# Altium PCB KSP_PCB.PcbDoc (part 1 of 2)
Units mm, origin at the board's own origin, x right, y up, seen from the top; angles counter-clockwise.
Board outline 121 x 121 mm, 2 copper layers (Top Layer, Bottom Layer), stack 1.571 mm thick; 210 components, 141 nets, 724 pads, 132 vias.
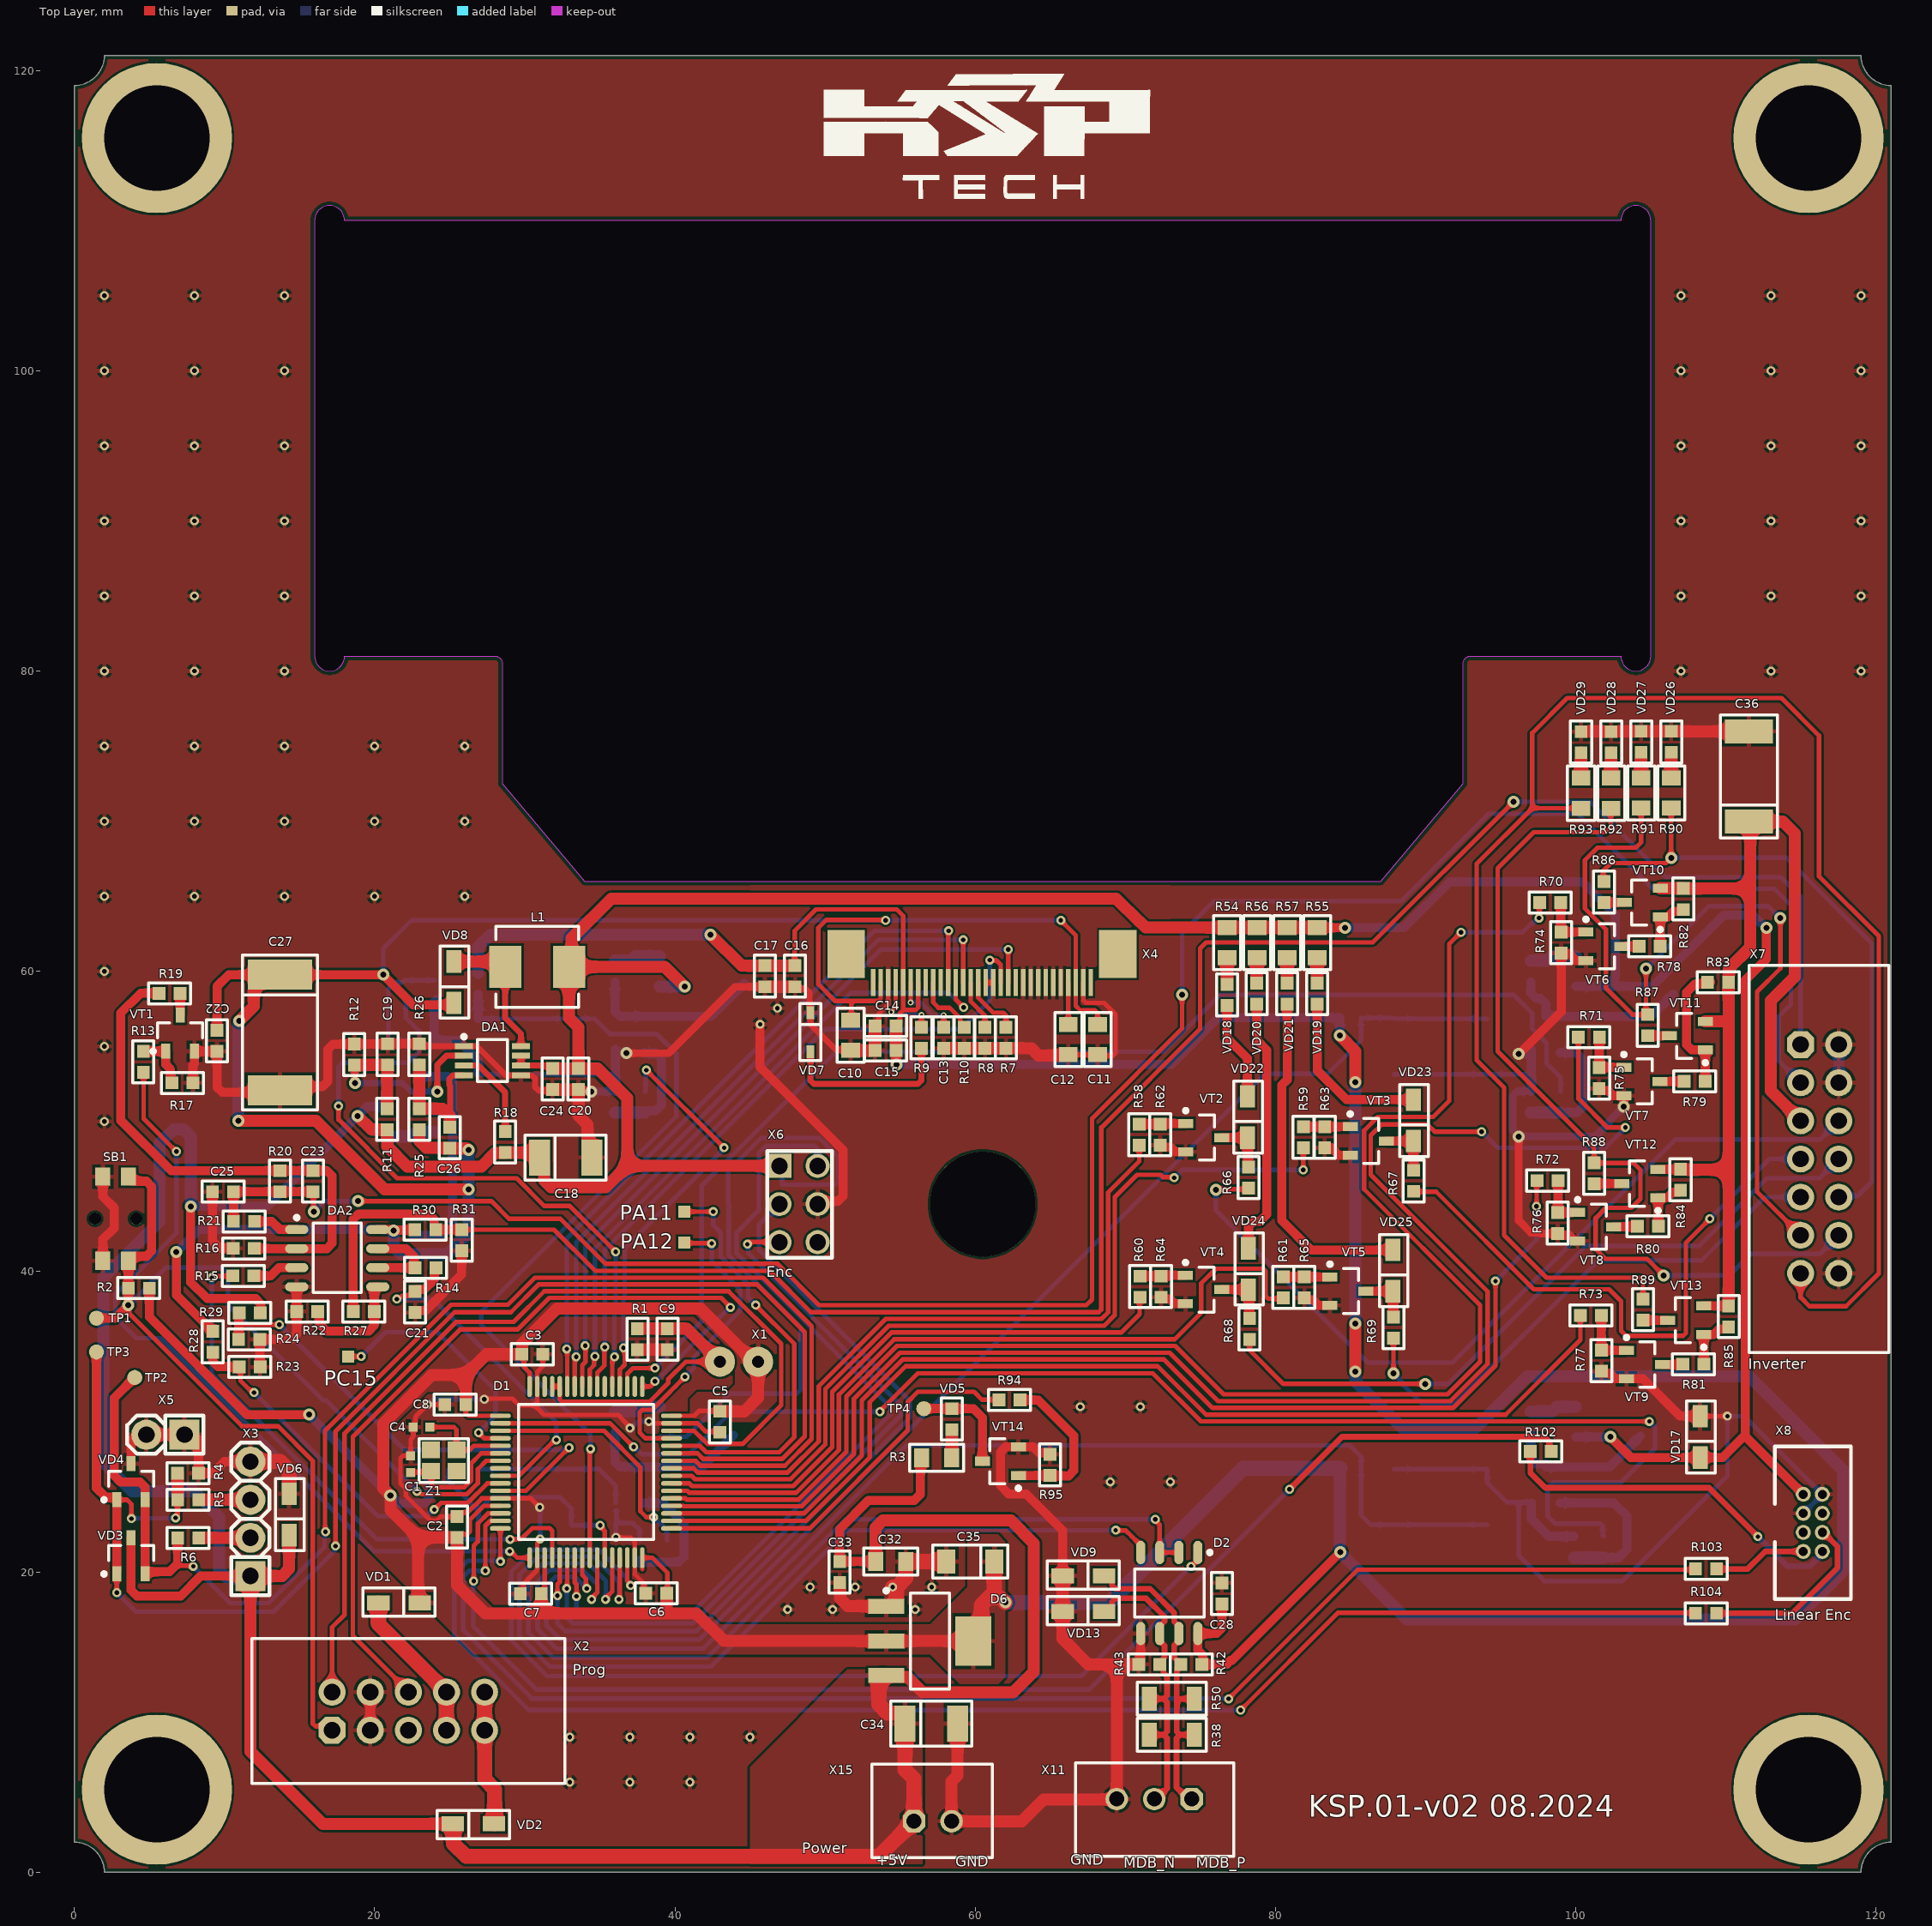
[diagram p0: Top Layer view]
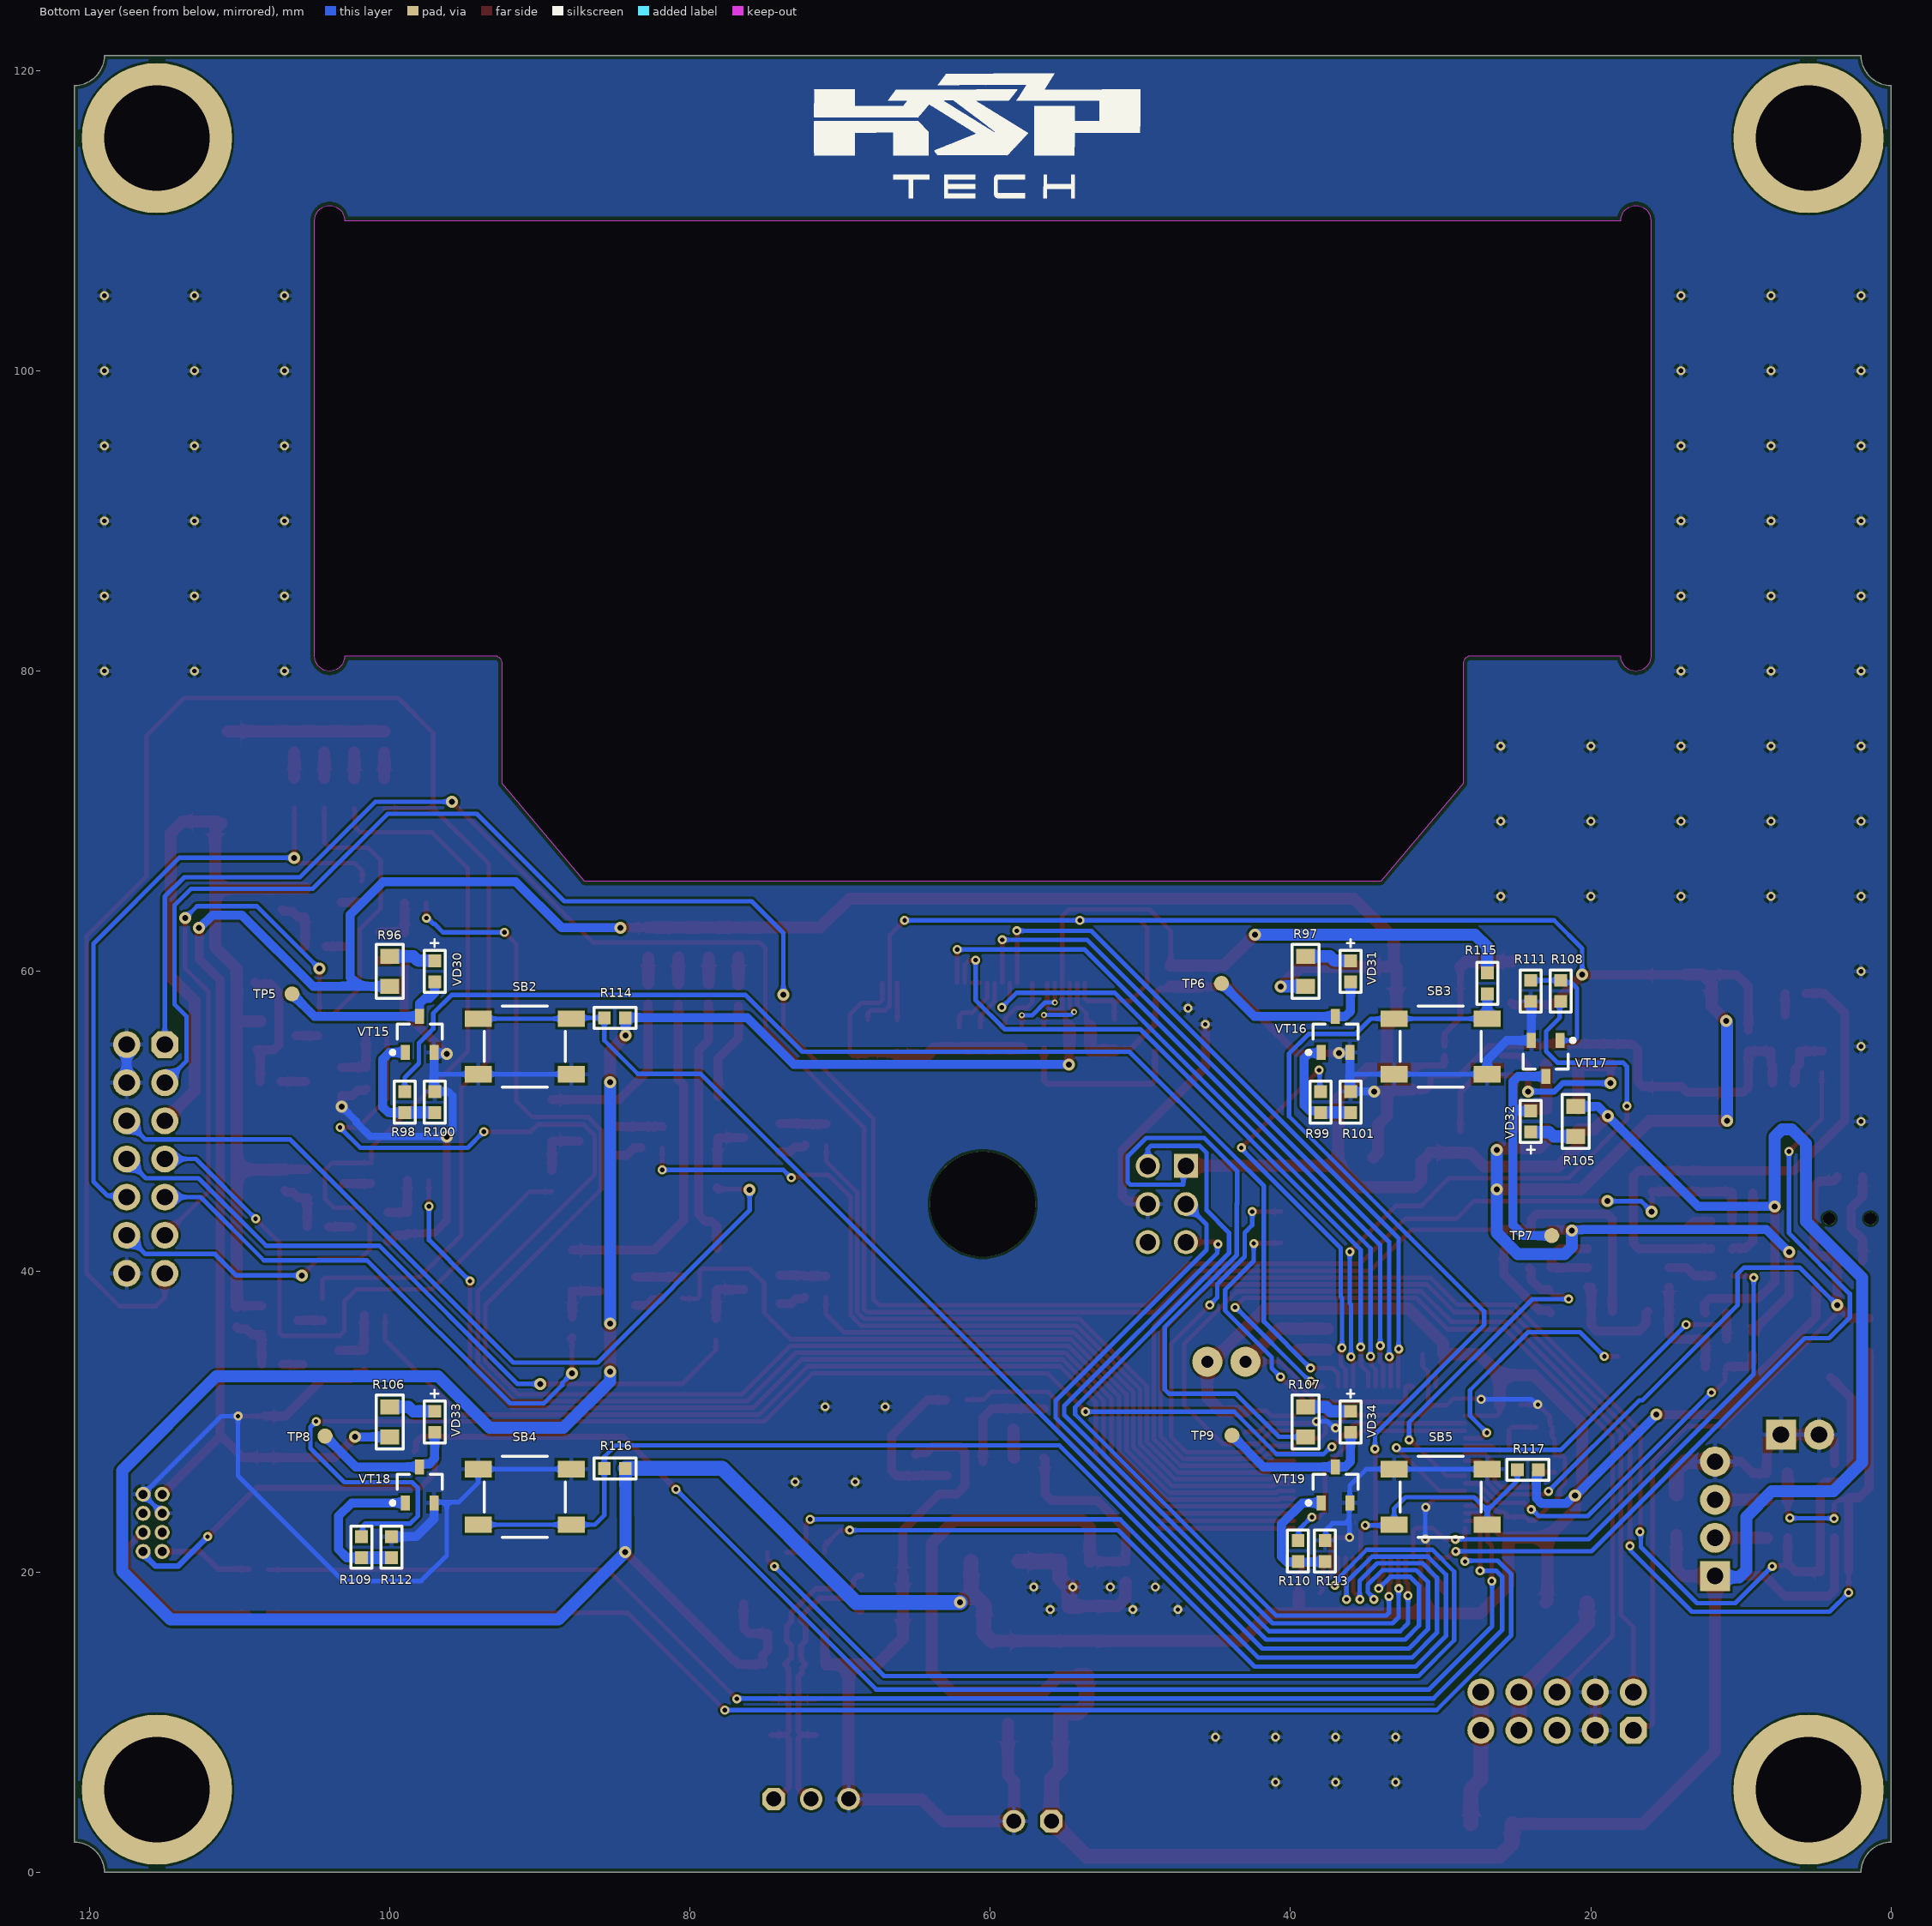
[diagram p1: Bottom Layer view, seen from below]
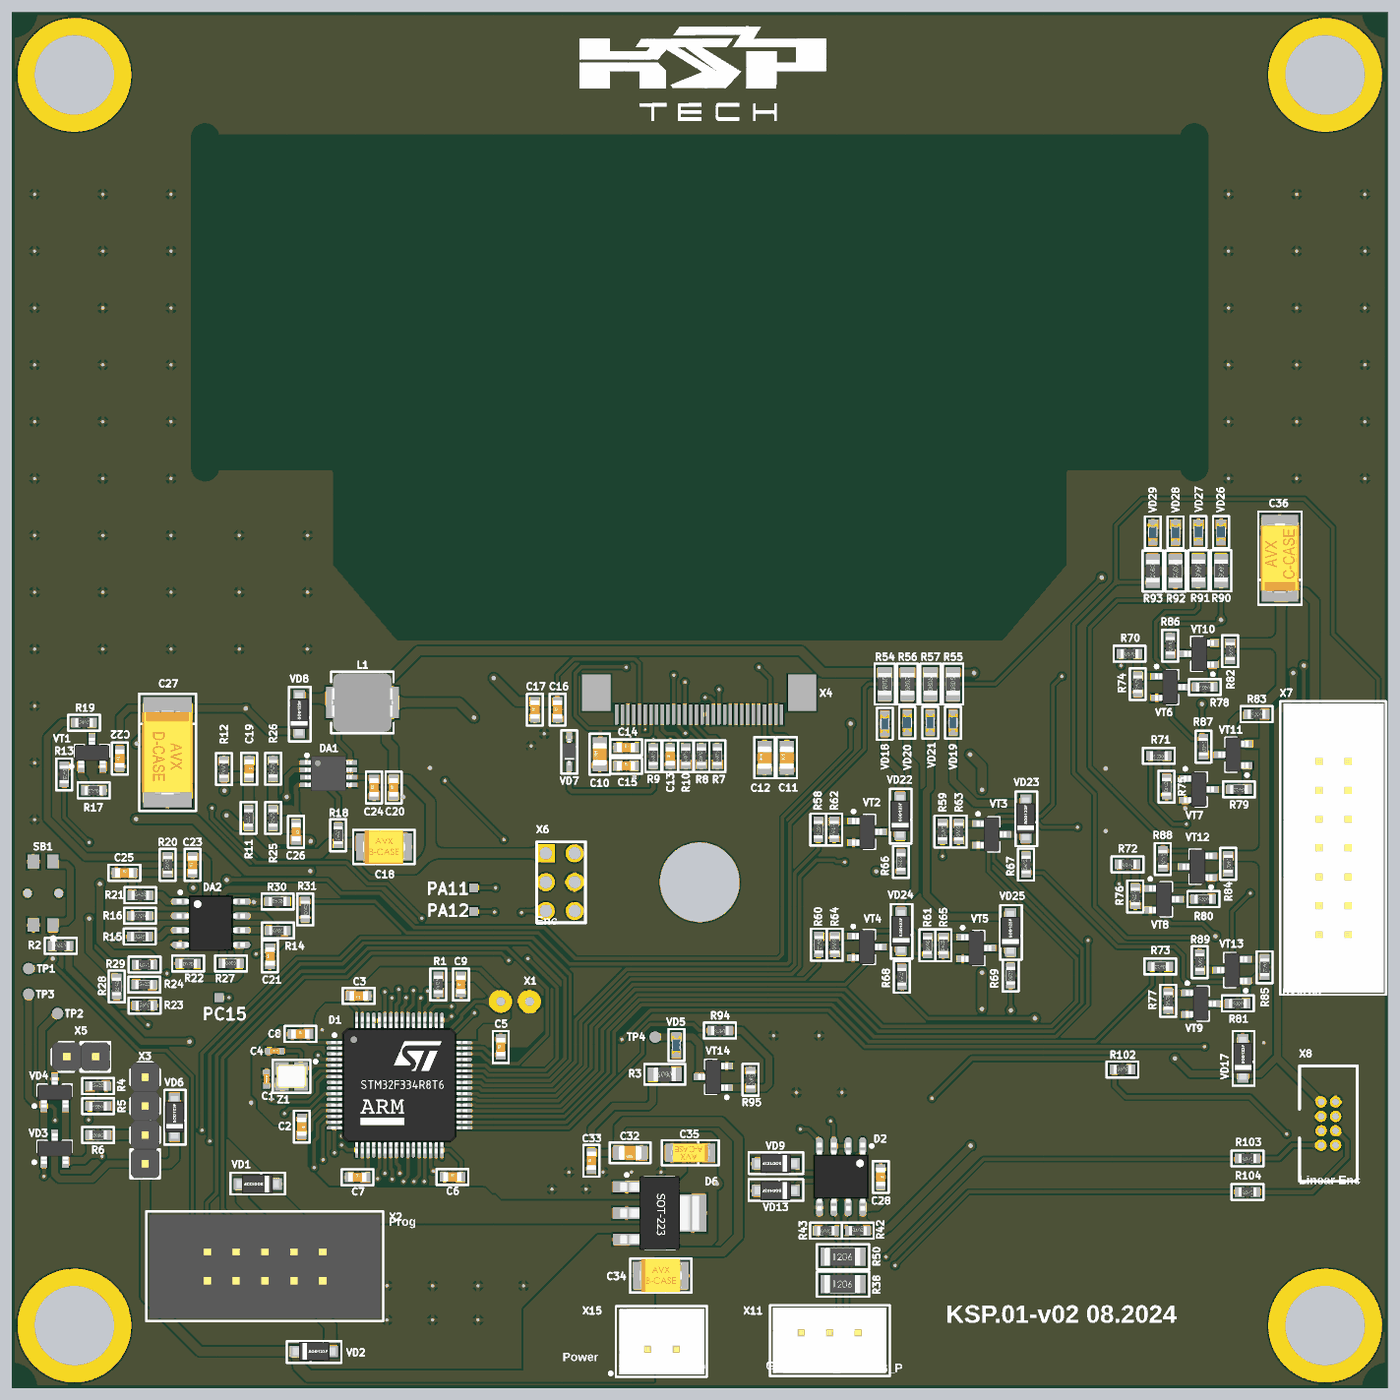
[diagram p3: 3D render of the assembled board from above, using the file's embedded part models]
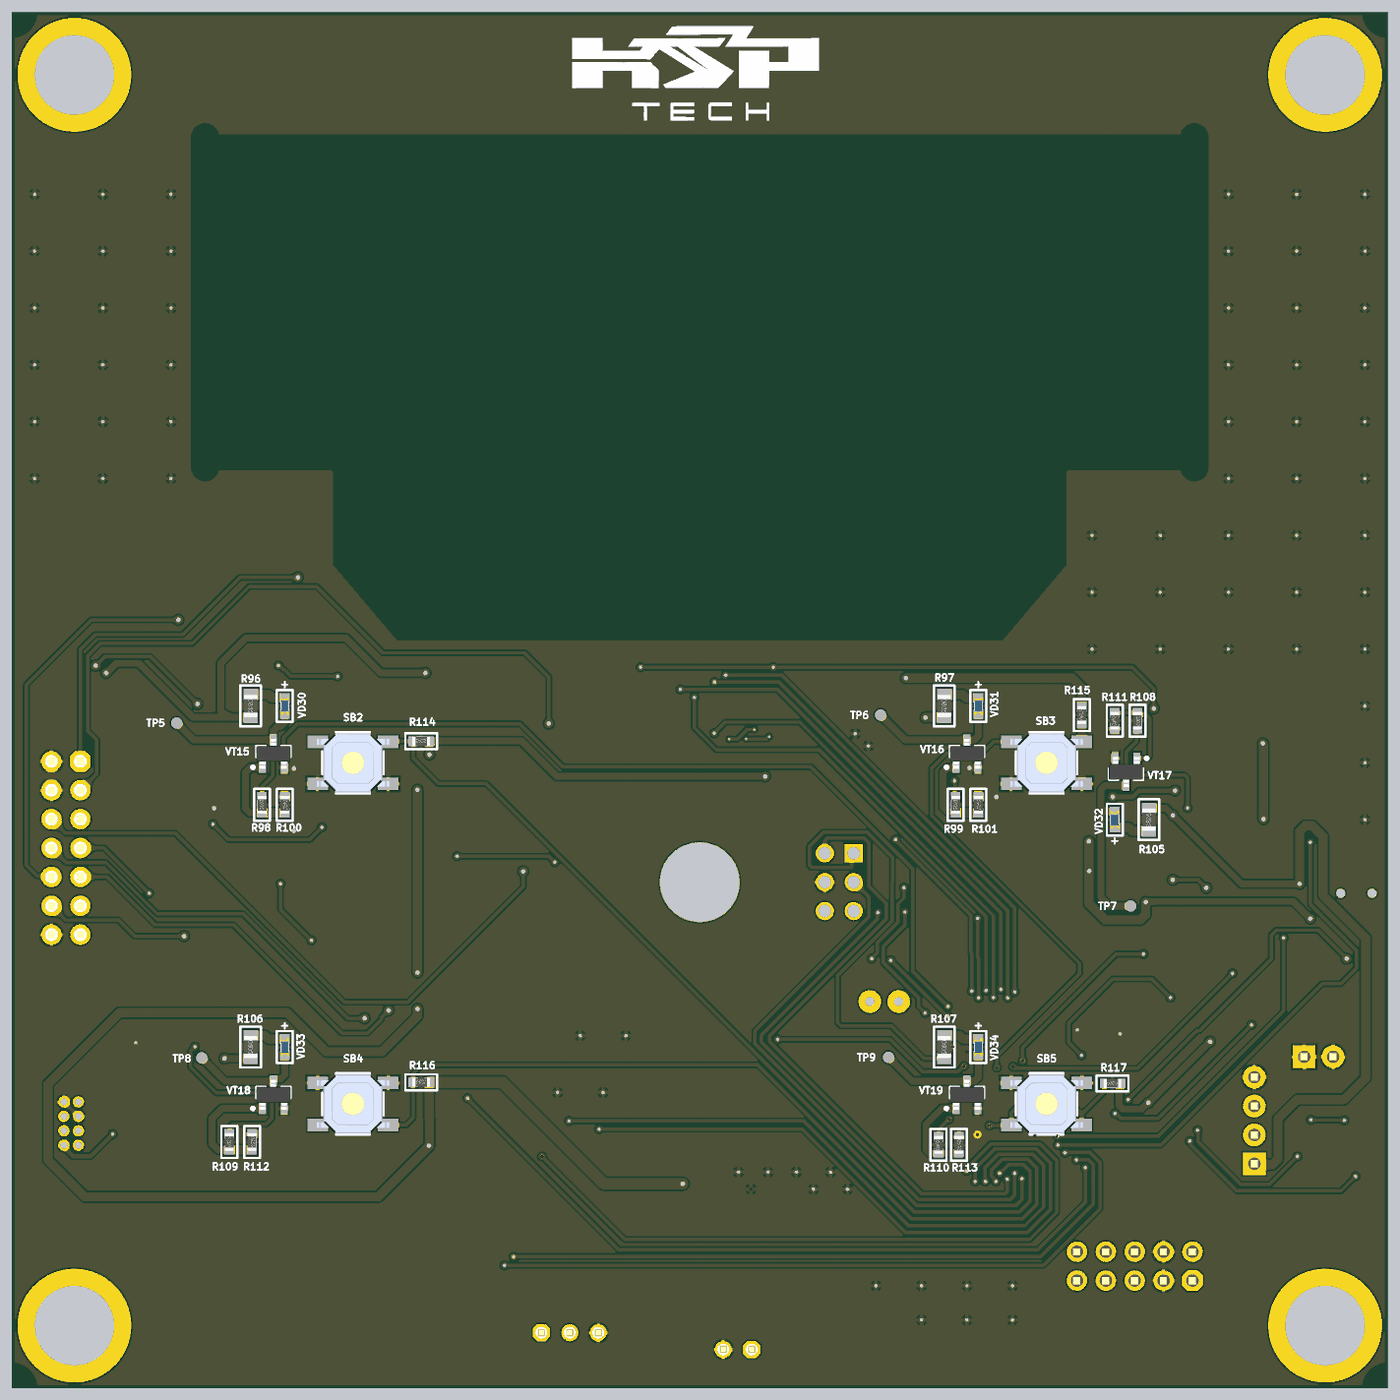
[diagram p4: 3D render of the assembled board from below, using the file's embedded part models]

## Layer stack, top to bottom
Top Solder: solder mask 0.0102, Solder Resist, Dk 3.5
Top Layer: signal copper 0.0356
Dielectric 1: dielectric 1.5, FR-4, Dk 4.8
Bottom Layer: signal copper 0.0356
Bottom Solder: solder mask 0.0102, Solder Resist, Dk 3.5

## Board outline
0,2 0,119 ccw(c0,121) 2,121 119,121 ccw(c121,121) 121,119 121,2 ccw(c121,0) 119,0 2,0 ccw(c0,0)
cut-out: 18,81 28,81 cw(c28,80.5) 28.5,80.5 28.5,72.5 34,66 87,66 92.5,72.5 92.5,80.5 cw(c93,80.5) 93,81 103,81 ccw(c104,81) 104,80 ccw(c104,81) 105,81 105,110 ccw(c104,110) 104,111 ccw(c104,110) 103,110 18,110 ccw(c17,110) 17,111 ccw(c17,110) 16,110 16,81 ccw(c17,81) 17,80 ccw(c17,81)

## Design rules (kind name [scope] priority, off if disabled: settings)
AcuteAngle [All] p1: minimum=3.50000000000000E+0001 checktracksonly=FALSE
BoardOutlineClearance "BoardOutlineClearance 1" [All] p1: gap=0.25 ignorepadtopadclearanceinfootprint=FALSE except(0: Arc-SplitContinuation Track-SplitContinuation SMDPad-SplitContinuation THPad-SplitContinuation Via-SplitContinuation Fill-SplitContinuation Poly-SplitContinuation Region-SplitContinuation Text-SplitContinuation) // Milling
BoardOutlineClearance "BoardOutlineClearance 2" [All] p2: gap=0.4 ignorepadtopadclearanceinfootprint=FALSE except(0: Arc-SplitContinuation Track-SplitContinuation SMDPad-SplitContinuation THPad-SplitContinuation Via-SplitContinuation Fill-SplitContinuation Poly-SplitContinuation Region-SplitContinuation Text-SplitContinuation) // V-Cut
Clearance "Clearance-1 1/2 Oz" [All] p1: gap=0.15 ignorepadtopadclearanceinfootprint=FALSE // Standart
ComponentClearance [All] p1: gap=0 collisioncheckmode=3 verticalgap=0 showdistances=FALSE
DiffPairsRouting "DiffPairsRouting 1/2 Oz" [All] p1: maxlimit=0.254 minlimit=0.1 mostfreqgap=0.254 toplayer_minwidth=0.1 toplayer_maxwidth=0.381 toplayer_prefwidth=0.381 bottomlayer_minwidth=0.1 bottomlayer_maxwidth=0.381 bottomlayer_prefwidth=0.381 maxuncoupledlength=12.7
HoleSize "Minimum HoleSize VIA 1" [IsVia] p1: absolutevalues=TRUE maxlimit=5.9 minlimit=0.3 maxpercent=80.000 minpercent=20.000 // Standart
HoleToHoleClearance Hole2HoleClearance [All] p1: gap=0.25 allowstackedmicrovias=FALSE
MinimumAnnularRing "Minimum AR VIA Standart" [IsVia] p1: minimumring=0.15
MinimumAnnularRing "Minimum AR PAD Standart" [IsPAD] p2: minimumring=0.2
MinimumAnnularRing "Minimum AR VIA Advance" [IsVia] p3: minimumring=0.1
MinimumAnnularRing "Minimum AR PAD Advance" [IsPAD] p4: minimumring=0.15
MinimumSolderMaskSliver "SolderMask Bridge Standart" [All] p1: minsoldermaskwidth=0.15 // All Masks
MinimumSolderMaskSliver "SolderMask Bridge Advance" [All] p2: minsoldermaskwidth=0.1 // Mask LDI
PlaneClearance "PlaneClearance-1 1/2 Oz" [All] p1: clearance=0.2 // Standart
PlaneClearance "PlaneClearance-2 1/2 Oz" [All] p2: clearance=0.15 // Advance
PlaneConnect "TermalConnect-1 1/2 Oz" [All] p1: planeconnectstyle=Relief reliefexpansion=0.2 reliefentries=4 reliefconductorwidth=0.4 reliefairgap=0.2 // Standart
PlaneConnect "TermalConnect-2 1/2 Oz" [All] p2: pad.planeconnectstyle=Relief pad.reliefexpansion=0.15 pad.reliefentries=4 pad.reliefconductorwidth=0.15 pad.reliefairgap=0.15 via.planeconnectstyle=Direct via.reliefexpansion=0.15 via.reliefentries=4 via.reliefconductorwidth=0.15 via.reliefairgap=0.15 // Advance
PolygonConnect "PolygonConnect-1 1/2 Oz" [All] p1: thpad.connectstyle=Relief thpad.reliefconductorwidth=0.3 thpad.reliefentries=4 thpad.polygonreliefangle="90 Angle" thpad.airgapwidth=0.2 smdpad.connectstyle=Relief smdpad.reliefconductorwidth=0.3 smdpad.reliefentries=4 smdpad.polygonreliefangle="90 Angle" smdpad.airgapwidth=0.2 via.connectstyle=Direct via.reliefconductorwidth=0.254 via.reliefentries=4 via.polygonreliefangle="90 Angle" via.airgapwidth=0.254 // Standart
RoutingCorners [All] p1 off: cornerstyle=45-Degree minsetback=2.54 maxsetback=2.54
RoutingVias [All] p1: holewidth=0.3 width=0.6 viastyle="Through Hole" minholewidth=0.2 minwidth=0.4 maxholewidth=5.9 maxwidth=6.4
SilkToSilkClearance Silk2SilkClearance [All] p1 off: silktosilkclearance=0.15
SilkToSolderMaskClearance Silk2SolderMaskClearance [IsPad] p1 off: minsilkscreentomaskgap=0.15 clearancetoexposedcopper=TRUE
SolderMaskExpansion SolderMaskExpansion-1 [All] p1: expansion=0.05 istentingtop=FALSE // Standart
SolderMaskExpansion "SolderMaskExpansion LDI" [All] p2: expansion=0.025 istentingtop=FALSE // Advance
SupplyNets "Schematic Supply Nets_2" [InNet('12V')] p1: voltage=12,00
SupplyNets "Schematic Supply Nets_1" [InNet('5V')] p2: voltage=5,000
SupplyNets "Schematic Supply Nets" [InNet('3.3V')] p3: voltage=3,000
UnRoutedNet [All] p1: checkbadconnections=TRUE
Width "Width 1/2 Oz" [All] p1: maxlimit=10 minlimit=0.1 preferedwidth=1 checkconnectedcopper=TRUE
19 further rules are at their usual default settings.

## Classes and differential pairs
component class 3_RK: C36 R54 R55 R56 R57 R58 R59 R60 R61 R62 R63 R64 R65 R66 R67 R68 R69 R70 R71 R72 R73 R74 R75 R76 R77 R78 R79 R80 R81 R82 R83 R84 R85 R86 R87 R88 R89 R90 R91 R92 R93 VD18 VD19 VD20 VD21 VD22 VD23 VD24 VD25 VD26 VD27 VD28 VD29 VT2 VT3 VT4 VT5 VT6 VT7 VT8 VT9 VT10 VT11 VT12 VT13
component class 2_Connection: C18 C19 C20 C21 C22 C23 C24 C25 C26 C27 C28 C32 C33 C34 C35 D2 D6 DA1 DA2 L1 R11 R12 R13 R14 R15 R16 R17 R18 R19 R20 R21 R22 R23 R24 R25 R26 R27 R28 R29 R30 R31 R38 R42 R43 R50 R96 R97 R98 R99 R100 R101 R102 R103 R104 R105 R106 R107 R108 R109 R110 R111 R112 R113 R114 R115 R116 R117 SB2 SB3 SB4 SB5 TP5 TP6 TP7 TP8 TP9 VD8 VD9 VD13 VD17 VD30 VD31 VD32 VD33 VD34 VT1 VT15 VT16 VT17 VT18 VT19 X6 X7 X8 X11 X15
component class 1_uC: C1 C2 C3 C4 C5 C6 C7 C8 C9 C10 C11 C12 C13 C14 C15 C16 C17 D1 R1 R2 R3 R4 R5 R6 R7 R8 R9 R10 R94 R95 SB1 TP1 TP2 TP3 TP4 VD1 VD2 VD3 VD4 VD5 VD6 VD7 VT14 X1 X2 X3 X4 X5 Z1
differential pair MODBUS: +MODBUS_P -MODBUS_N

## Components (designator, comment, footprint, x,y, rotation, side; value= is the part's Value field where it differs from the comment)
C1 "10p" CH0402C 22.4,27.175 r270 top
C2 "0.1u" CH0603C 25.5,23 r270 top
C3 "0.1u" CH0603C 30.5,34.5 r180 top
C4 "10p" CH0402C 23.125,29.65 r0 top
C5 "0.1u" CH0603C 43,30 r90 top
C6 "0.1u" CH0603C 38.75,18.575 r0 top
C7 "0.1u" CH0603C 30.399,18.549 r0 top
C8 "0.1u" CH0603C 25.375,31.15 r0 top
C9 "0.1u" CH0603C 39.5,35.5 r90 top
C10 "4.7u, 25V" CH0805C 51.7,55.75 r90 top
C11 "4.7u, 25V" CH0805C 68.15,55.45 r90 top
C12 "4.7u, 25V" CH0805C 66.2,55.45 r90 top
C13 "1u" CH0603C 57.9,55.575 r90 top
C14 "4.7u" CH0603C 54.025,56.35 r0 top
C15 "0.1u" CH0603C 54.025,54.725 r0 top
C16 "4.7u" CH0603C 48,59.675 r90 top
C17 "0.1u" CH0603C 46,59.675 r90 top
C18 "47uF" TANTAL_B 32.725,47.6 r0 top
C19 "0.1u" CH0603C 20.875,54.475 r270 top
C20 "10u" CH0603C 33.575,52.825 r90 top
C21 "0.022u, 50V" CH0603C 22.7,37.975 r90 top
C22 "0.1u, 25V" CH0603C 9.5,55.375 r90 top
C23 "1n" CH0603C 15.9,46.025 r90 top
C24 "0.1u" CH0603C 31.85,52.825 r90 top
C25 "0.022u, 50V" CH0603C 9.9,45.325 r0 top
C26 "39p" CH0603C 25,48.925 r270 top
C27 "68uF" TANTAL_D 13.7,55.925 r270 top
C28 "0.1u" CH0603C 76.425,18.575 r270 top
C32 "10u" CH0805C 54.375,20.7 r180 top
C33 "0.1 u" CH0603C 50.975,20 r90 top
C34 "68uF" TANTAL_B 57.075,9.9 r0 top
C35 "47uF" TANTAL_A 59.675,20.7 r180 top
C36 "4.7uF" TANTAL_C 111.525,72.99 r90 top
D1 "STM32F103RBT6" 64-LQFP 34.075,26.65 r0 top
D2 "ADM3485ARZ" 8-SOIC 72.925,18.6 r270 top
D6 "LM1117GS-3.3" SOT223 56.975,15.4 r0 top
DA1 "LM2621AMMX" 8-SSOP 27.85,54.05 r0 top
DA2 "OP295GSZ-REEL7" 8-SOIC 17.508,40.899 r0 top
L1 "10u" "IND: IHLP2020" 30.825,60.3 r0 top
R1 "10k" CH0603R 37.5,35.5 r90 top
R2 "10k" CH0603R 4.3,38.9 r0 top
R3 "1k" CH0805R 57.425,27.6 r180 top
R4 "10k" CH0603R 7.575,26.575 r0 top
R5 "100" CH0603R 7.583,24.806 r180 top
R6 "100" CH0603R 7.583,22.266 r180 top
R7 "10k" CH0603R 62.05,55.575 r90 top
R8 "10k" CH0603R 60.65,55.575 r90 top
R9 "50" CH0603R 56.425,55.575 r90 top
R10 "604k" CH0603R 59.275,55.575 r90 top
R11 "10k" CH0603R 20.825,50.15 r90 top
R12 "DNP" CH0603R 18.65,54.45 r90 top
R13 "100" CH0603R 4.6,53.975 r270 top
R14 "100" CH0603R 23.4,40.25 r180 top
R15 "3.32k" CH0603R 11.25,39.725 r180 top
R16 "17.8k" CH0603R 11.275,41.55 r180 top
R17 "4.7k" CH0603R 7.2,52.575 r180 top
R18 "76.8k" CH0603R 28.7,48.625 r90 top
R19 "6.49k" CH0603R 6.35,58.525 r0 top
R20 "10k" CH0603R 13.7,46.025 r90 top
R21 "10" CH0603R 11.3,43.35 r0 top
R22 "4.7k" CH0603R 15.5,37.35 r180 top
R23 "2.7k" CH0603R 11.675,33.65 r0 top
R24 "10k" CH0603R 11.644,35.491 r0 top
R25 "130k" CH0603R 22.975,50.15 r90 top
R26 "15k" CH0603R 22.975,54.475 r90 top
R27 "10k" CH0603R 19.275,37.35 r0 top
R28 "10k" CH0603R 9.225,35.325 r270 top
R29 "10k" CH0603R 11.675,37.25 r180 top
R30 "1M" CH0603R 23.375,42.8 r0 top
R31 "10k" CH0603R 25.8,42.1 r270 top
R38 "120" CH1206R 73.1,9.15 r0 top
R42 "1.2k" CH0603R 74.4,13.85 r0 top
R43 "1.2k" CH0603R 71.6,13.85 r180 top
R50 "Var" CH1206R 73.1,11.55 r0 top
R54 "1k" CH0805R 76.775,61.925 r90 top
R55 "1k" CH0805R 82.775,61.925 r90 top
R56 "1k" CH0805R 78.775,61.925 r90 top
R57 "1k" CH0805R 80.775,61.925 r90 top
R58 "100" CH0603R 70.925,49.125 r270 top
R59 "100" CH0603R 81.85,48.95 r270 top
R60 "100" CH0603R 70.975,39 r270 top
R61 "100" CH0603R 80.525,38.95 r270 top
R62 "4.7k" CH0603R 72.325,49.125 r90 top
R63 "4.7k" CH0603R 83.275,48.95 r90 top
R64 "4.7k" CH0603R 72.375,39 r90 top
R65 "4.7k" CH0603R 81.925,38.95 r90 top
R66 "10" CH0603R 78.2,46.275 r90 top
R67 "10" CH0603R 89.2,46.05 r90 top
R68 "10" CH0603R 78.275,36.175 r90 top
R69 "10" CH0603R 87.85,36.275 r90 top
R70 "100" CH0603R 98.3,64.59 r180 top
R71 "100" CH0603R 100.875,55.615 r180 top
R72 "100" CH0603R 98.125,46.065 r180 top
R73 "100" CH0603R 101,37.09 r180 top
R74 "4.7k" CH0603R 99.025,61.915 r90 top
R75 "4.7k" CH0603R 101.55,52.89 r90 top
R76 "4.7k" CH0603R 98.8,43.24 r90 top
R77 "4.7k" CH0603R 101.7,34.065 r90 top
R78 "100" CH0603R 104.925,61.665 r180 top
R79 "100" CH0603R 107.925,52.665 r180 top
R80 "100" CH0603R 104.8,43.015 r180 top
R81 "100" CH0603R 107.825,33.84 r180 top
R82 "4.7k" CH0603R 107.15,64.815 r270 top
R83 "4.7k" CH0603R 109.475,59.275 r180 top
R84 "4.7k" CH0603R 106.975,46.115 r270 top
R85 "4.7k" CH0603R 110.175,37.015 r270 top
R86 "10" CH0603R 101.875,65.29 r270 top
R87 "10" CH0603R 104.8,56.415 r270 top
R88 "10" CH0603R 101.225,46.54 r270 top
R89 "10" CH0603R 104.475,37.465 r270 top
R90 "1k" CH0805R 106.35,71.89 r270 top
R91 "1k" CH0805R 104.35,71.89 r270 top
R92 "1k" CH0805R 102.35,71.865 r270 top
R93 "1k" CH0805R 100.35,71.865 r270 top
R94 "100" CH0603R 62.275,31.45 r180 top
R95 "4.7k" CH0603R 64.975,27.125 r270 top
R96 "1k" CH0805R 100,60 r270 bottom
R97 "1k" CH0805R 39,60 r270 bottom
R98 "100" CH0603R 99,51.3 r90 bottom
R99 "100" CH0603R 38,51.3 r90 bottom
R100 "4.7k" CH0603R 97,51.3 r270 bottom
R101 "4.7k" CH0603R 36,51.3 r270 bottom
R102 "DNP" CH0603R 97.675,28.025 r0 top
R103 "DNP" CH0603R 108.675,20.2 r180 top
R104 "DNP" CH0603R 108.675,17.25 r180 top
R105 "1k" CH0805R 21,50 r90 bottom
R106 "1k" CH0805R 100,30 r270 bottom
R107 "1k" CH0805R 39,30 r270 bottom
R108 "100" CH0603R 22,58.7 r270 bottom
R109 "100" CH0603R 101.874,21.65 r90 bottom
R110 "100" CH0603R 39.5,21.4 r90 bottom
R111 "4.7k" CH0603R 24,58.7 r90 bottom
R112 "4.7k" CH0603R 99.874,21.65 r270 bottom
R113 "4.7k" CH0603R 37.7,21.4 r270 bottom
R114 "10k" CH0603R 85,56.9 r180 bottom
R115 "10k" CH0603R 26.9,59.2 r90 bottom
R116 "10k" CH0603R 85,26.9 r180 bottom
R117 "10k" CH0603R 24.2,26.8 r180 bottom
SB1 "\"Кнопка\"" TL1014BF160QG 4.125,43.525 r270 top
SB2 "\"Кнопка\"" "BUT: SKQGADE010" 91,55 r180 bottom locked
SB3 "\"Кнопка\"" "BUT: SKQGADE010" 30,55 r180 bottom locked
SB4 "\"Кнопка\"" "BUT: SKQGADE010" 91,25 r0 bottom locked
SB5 "\"Кнопка\"" "BUT: SKQGADE010" 30,25 r0 bottom locked
TP1 "=value" TestPoint#1 1.475,36.9 r90 top
TP2 "=value" TestPoint#1 4.025,32.95 r90 top
TP3 "=value" TestPoint#1 1.475,34.65 r90 top
TP4 "=value" TestPoint#1 56.575,30.875 r180 top
TP5 "=value" TestPoint#1 106.5,58.5 r90 bottom
TP6 "=value" TestPoint#1 44.6,59.2 r90 bottom
TP7 "=value" TestPoint#1 22.6,42.4 r90 bottom
TP8 "=value" TestPoint#2 104.3,28.125 r90 bottom
TP9 "=value" TestPoint#1 43.9,29.1 r90 bottom
VD1 "PMEG6010CEH" SOD123F 21.625,17.95 r0 top
VD2 "PMEG6010CEH" SOD123F 26.575,3.225 r180 top
VD3 "BAT54C" SOT23_123 3.777,21.066 r90 top
VD4 "PESD5V0L2BT" SOT23_132 3.777,26.006 r90 top
VD5 "*" CH0603LB 58.45,30.175 r90 top
VD6 "SMF5.0A" SOD123F 14.3,23.825 r270 top
VD7 "1N4148WS" SOD323 49.025,55.95 r90 top
VD8 "PMEG6010CEH" SOD123F 25.275,59.275 r270 top
VD9 "SMF5.0A" SOD123F 67.2,19.75 r0 top
VD13 "SMF5.0A" SOD123F 67.2,17.375 r0 top
VD17 "SMF5.0A" SOD123F 108.275,29 r270 top
VD18 "RED" CH0603LB 76.775,58.425 r270 top
VD19 "RED" CH0603LB 82.775,58.525 r270 top
VD20 "RED" CH0603LB 78.75,58.525 r270 top
VD21 "RED" CH0603LB 80.775,58.525 r270 top
VD22 "PMEG6010CEH" SOD123F 78.125,50.3 r270 top
VD23 "PMEG6010CEH" SOD123F 89.175,50.075 r270 top
VD24 "PMEG6010CEH" SOD123F 78.2,40.175 r270 top
VD25 "PMEG6010CEH" SOD123F 87.825,40.075 r270 top
VD26 "RED" CH0603LB 106.35,75.29 r90 top
VD27 "GREEN" CH0603LB 104.35,75.29 r90 top
VD28 "YELLOW" CH0603LB 102.35,75.265 r90 top
VD29 "BLUE" CH0603LB 100.35,75.265 r90 top
VD30 "BLUE" CH0603LB 97,60 r270 bottom
VD31 "BLUE" CH0603LB 36,60 r270 bottom
VD32 "BLUE" CH0603LB 24,50 r90 bottom
VD33 "BLUE" CH0603LB 97,30 r270 bottom
VD34 "BLUE" CH0603LB 36,30 r270 bottom
VT1 "2N7002" SOT23_123 7.05,55.875 r90 top
VT2 "2N7002" SOT23_123 75.225,48.925 r0 top
VT3 "2N7002" SOT23_123 86.175,48.7 r0 top
VT4 "2N7002" SOT23_123 75.206,38.807 r0 top
VT5 "2N7002" SOT23_123 84.825,38.7 r0 top
VT6 "2N7002" SOT23_123 101.875,61.665 r0 top
VT7 "2N7002" SOT23_123 104.4,52.665 r0 top
VT8 "2N7002" SOT23_123 101.325,42.99 r0 top
VT9 "2N7002" SOT23_123 104.575,33.815 r0 top
VT10 "BSH201,215" SOT23_123 104.425,64.59 r180 top
VT11 "BSH201,215" SOT23_123 107.425,55.715 r180 top
VT12 "BSH201,215" SOT23_123 104.275,45.865 r180 top
VT13 "BSH201,215" SOT23_123 107.325,36.765 r180 top
VT14 "2N7002" SOT23_123 61.675,27.375 r180 top
VT15 "2N7002" SOT23_123 98,55.8 r90 bottom
VT16 "2N7002" SOT23_123 37,55.8 r90 bottom
VT17 "2N7002" SOT23_123 23,54.2 r270 bottom
VT18 "2N7002" SOT23_123 98,25.8 r90 bottom
VT19 "2N7002" SOT23_123 37,25.8 r90 bottom
X1 "JMP-2" PLS-2 43,34 r0 top
X2 "KLS1-202-10-T-B" "CON: IDC-10MS" 22.245,10.73 r0 top
X3 "DS1021-1X4" "CON: PLS-4" 11.725,23.541 r90 top
X4 "Conn" FPC-30 53.2,59.25 r0 top
X5 "DNP" "CON: PLS-2" 6.066,29.141 r180 top
X6 "DS1021-2X3" "CON: PLD-6 (without body)" 46.96,47.04 r270 top locked
X7 "KLS1-202-14-T-B" "CON: IDC-14MS" 116.245,47.505 r270 top
X8 "DC3 2X4P" "CON: DC3 2X4P" 115.15,25.175 r270 top
X11 "KLS1-2.50-03-S" "CON: CWF-3" 71.925,4.875 r180 top
X15 "KLS1-2.50-02-S" "CON: CWF-2" 57.175,3.4 r0 top
Z1 "12MHz" "OSC: 2520" 25.45,28.125 r180 top

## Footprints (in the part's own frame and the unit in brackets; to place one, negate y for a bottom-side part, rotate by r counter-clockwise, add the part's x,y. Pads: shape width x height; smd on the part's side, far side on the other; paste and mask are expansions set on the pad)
8-SOIC [mm]
  rrect100% 1.55x0.6 smd: 1(-2.7,1.905) 2(-2.7,0.635) 3(-2.7,-0.635) 4(-2.7,-1.905) 5(2.7,-1.905) 6(2.7,-0.635) 7(2.7,0.635) 8(2.7,1.905)
  round 0.7 on Mech1: 28(-2.395,1.8)
  silkscreen extent -2.82,-2.3 1.6,2.83, body extent -3,-2.45 3,2.45, height 1.75
8-SSOP [mm] "VSSOP, 8-Leads, Body 3,10x3,10mm, Pitch 0,65mm"
  rect 1.2x0.4 smd: 1(-1.9,0.975) 2(-1.9,0.325) 3(-1.9,-0.325) 4(-1.9,-0.975) 5(1.9,-0.975) 6(1.9,-0.325) 7(1.9,0.325) 8(1.9,0.975)
  round 0.5 on Mech1: ""(-1.6,1.1)
  silkscreen extent -2.02,-1.4 1,1.72, body extent -2.05,-1.55 2.05,1.55, height 1.1
64-LQFP [mm] "Thin QFP, 64-Leads, Body 10x10mm, Pitch 0.5mm, IPC Medium Density"
  oval 1.4x0.3 smd: 1(-5.7,3.75) 2(-5.7,3.25) 3(-5.7,2.75) 4(-5.7,2.25) 5(-5.7,1.75) 6(-5.7,1.25) 7(-5.7,0.75) 8(-5.7,0.25) 9(-5.7,-0.25) 10(-5.7,-0.75) 11(-5.7,-1.25) 12(-5.7,-1.75) 13(-5.7,-2.25) 14(-5.7,-2.75) 15(-5.7,-3.25) 16(-5.7,-3.75) 33(5.7,-3.75) 34(5.7,-3.25) 35(5.7,-2.75) 36(5.7,-2.25) 37(5.7,-1.75) 38(5.7,-1.25) 39(5.7,-0.75) 40(5.7,-0.25) 41(5.7,0.25) 42(5.7,0.75) 43(5.7,1.25) 44(5.7,1.75) 45(5.7,2.25) 46(5.7,2.75) 47(5.7,3.25) 48(5.7,3.75)
  round 0.5 on Mech1: 1(-5.4,5.4)
  oval 0.3x1.4 smd: 17(-3.75,-5.7) 18(-3.25,-5.7) 19(-2.75,-5.7) 20(-2.25,-5.7) 21(-1.75,-5.7) 22(-1.25,-5.7) 23(-0.75,-5.7) 24(-0.25,-5.7) 25(0.25,-5.7) 26(0.75,-5.7) 27(1.25,-5.7) 28(1.75,-5.7) 29(2.25,-5.7) 30(2.75,-5.7) 31(3.25,-5.7) 32(3.75,-5.7) 49(3.75,5.7) 50(3.25,5.7) 51(2.75,5.7) 52(2.25,5.7) 53(1.75,5.7) 54(1.25,5.7) 55(0.75,5.7) 56(0.25,5.7) 57(-0.25,5.7) 58(-0.75,5.7) 59(-1.25,5.7) 60(-1.75,5.7) 61(-2.25,5.7) 62(-2.75,5.7) 63(-3.25,5.7) 64(-3.75,5.7)
  round 0.5 on Top Overlay: ""(-5.7,4.4)
  silkscreen extent -4.5,-4.5 4.5,4.5, body extent -6,-6 6,6, height 1.5
"BUT: SKQGADE010" [mm]
  rect 1.8x1.1 smd: 1(-3.1,1.85) 1(3.1,1.85) 2(-3.1,-1.85) 2(3.1,-1.85)
  silkscreen extent -2.7,-2.7 2.7,2.7, body extent -3.2,-2.6 3.2,2.6, height 1.45
CH0402C [mm]
  rect 0.6x0.6 smd: 1(-0.55,0) 2(0.55,0)
  body extent -0.51,-0.25 0.51,0.25, height 0.51
CH0603C [mm] "Chip Capacitor, 2-Leads, Body 1,53x0,85mm, IPC Medium Density"
  rect 0.85x0.85 smd: 1(-0.7,0) 2(0.7,0)
  silkscreen extent -1.4,-0.7 1.4,0.7, body extent -0.8,-0.4 0.8,0.4, height 0.3
CH0603LB [mm] "Chip Capacitor, 2-Leads, Body 1,53x0,85mm, IPC Medium Density"
  rect 0.85x0.85 smd: 1(-0.7,0) 2(0.7,0)
  silkscreen extent -1.4,-0.7 1.4,0.7, body extent -0.8,-0.4 0.8,0.4, height 0.6
CH0603R [mm]
  rect 0.85x0.85 smd: 1(-0.7,0) 2(0.7,0)
  silkscreen extent -1.4,-0.7 1.4,0.7, body extent -0.8,-0.4 0.8,0.4, height 0.44
CH0805C [mm] "Chip Capacitor, 2-Leads, Body 2,00x1,20mm, IPC Medium Density"
  rect 1x1.25 smd: 1(-1,0) 2(1,0)
  silkscreen extent -1.8,-0.9 1.8,0.9, body extent -1,-0.62 1,0.63, height 0.78
CH0805R [mm]
  rect 1x1.25 smd: 1(-1,0) 2(1,0)
  silkscreen extent -1.8,-0.9 1.8,0.9, body extent -1,-0.6 1,0.6, height 0.44
CH1206R [mm] "Chip Resistor, 2-Leads, Body 3,0x1,5mm, IPC Low Density"
  rect 1x1.6 smd: 1(-1.5,0) 2(1.5,0)
  silkscreen extent -2.3,-1.1 2.3,1.1, body extent -1.65,-0.8 1.55,0.8, height 0.47
"CON: CWF-2" [mm]
  oct 1.5x1.5 hole 1: 1(-1.25,0)
  round 1.5 hole 1: 2(1.25,0)
  round 0.5 on Mech1: 23(-3.2,-1.7)
  round 0.5 on Top Overlay: 24(-4.5,-2.1)
  silkscreen extent -4.04,-2.41 3.96,3.81, body extent -3.75,-2.18 3.75,3.57, height 7
"CON: CWF-3" [mm]
  oct 1.5x1.5 hole 1: 1(-2.5,0)
  round 1.5 hole 1: 2(0,0) 3(2.5,0)
  round 0.5 on Mech1: 28(-4.5,-1.7)
  silkscreen extent -5.29,-2.41 5.25,3.81, body extent -5,-2.2 5,3.55, height 7
"CON: DC3 2X4P" [mm]
  round 1 hole 0.6 mask+0.05: 1(0,0) 2(0,1.27) 3(1.27,0) 4(1.27,1.27) 5(2.54,0) 6(2.54,1.27) 7(3.81,0) 8(3.81,1.27)
  silkscreen extent -3.17,-1.91 6.98,3.18, body extent -3.1,-1.91 6.91,3.1, height 4.9
"CON: IDC-10MS" [mm] "IDC-10MS 10 pin PCB-mount header"
  oct 1.8x1.8 hole 1.1: 1(-5.08,-1.27)
  round 1.8 hole 1.1: 2(-5.08,1.27) 3(-2.54,-1.27) 4(-2.54,1.27) 5(0,-1.27) 6(0,1.27) 7(2.54,-1.27) 8(2.54,1.27) 9(5.08,-1.27) 10(5.08,1.27)
  silkscreen extent -10.41,-4.83 10.41,4.83, body extent -10.14,-4.57 10.16,4.53, height 9
"CON: IDC-14MS" [mm] "IDC-14MS connector"
  oct 1.8x1.8 hole 1.1: 1(-7.62,-1.27)
  round 1.8 hole 1.1: 2(-7.62,1.27) 3(-5.08,-1.27) 4(-5.08,1.27) 5(-2.54,-1.27) 6(-2.54,1.27) 7(0,-1.27) 8(0,1.27) 9(2.54,-1.27) 10(2.54,1.27) 11(5.08,-1.27) 12(5.08,1.27) 13(7.62,-1.27) 14(7.62,1.27)
  round 0.5 on Mech1: 38(-12.2,-3.9)
  silkscreen extent -12.9,-4.7 12.9,4.6, body extent -12.71,-4.4 12.72,4.4, height 9.1
"CON: PLD-6 (without body)" [mm]
  rect 1.6x1.6 hole 1.1: 1(0,0)
  round 1.6 hole 1.1: 2(0,2.54) 3(2.54,0) 4(2.54,2.54) 5(5.08,0) 6(5.08,2.54)
  silkscreen extent -1,-0.81 6.11,3.5
"CON: PLS-2" [mm]
  rect 2x2 hole 1.1: 1(-1.27,0)
  round 2 hole 1.1: 2(1.27,0)
  silkscreen extent -2.54,-1.27 2.54,1.27, body extent -2.57,-1.28 2.51,1.26, height 8.54
"CON: PLS-4" [mm] "PLS-40 4 pin header"
  rect 2x2 hole 1.1: 1(-3.81,0)
  round 2 hole 1.1: 2(-1.27,0) 3(1.27,0) 4(3.81,0)
  silkscreen extent -5.08,-1.27 5.08,1.27, body extent -5.08,-1.27 5.08,1.27, height 8.54
FPC-30 [mm]
  rect 0.3x1.8 smd mask+0.05: 1(14.5,0) 2(14,0) 3(13.5,0) 4(13,0) 5(12.5,0) 6(12,0) 7(11.5,0) 8(11,0) 9(10.5,0) 10(10,0) 11(9.5,0) 12(9,0) 13(8.5,0) 14(8,0) 15(7.5,0) 16(7,0) 17(6.5,0) 18(6,0) 19(5.5,0) 20(5,0) 21(4.5,0) 22(4,0) 23(3.5,0) 24(3,0) 25(2.5,0) 26(2,0) 27(1.5,0) 28(1,0) 29(0.5,0) 30(0,0)
  rect 2.5x3.2 smd mask+0.05: N(-1.8,1.9) N(16.3,1.9)
  body extent -3.05,-0.3 17.55,4.9, height 2
"IND: IHLP2020" [mm] "SMD inductor, 5.2x5.2x3 mm"
  rect 2.15x2.8 smd: 1(-2.125,0) 2(2.125,0)
  silkscreen extent -2.75,-2.7 2.75,2.7, body extent -2.73,-2.57 2.73,2.58, height 2.89
"OSC: 2520" [mm]
  rect 1.2x1.1 smd: 1(0,0) 2(1.7,0) 3(1.7,1.4) 4(0,1.4)
  round 0.5 on Mech1: 5(-0.075,0.025)
  round 0.5 on Top Overlay: 6(-1.275,-0.6)
  silkscreen extent -0.8,-0.75 2.5,2.15, body extent -0.45,-0.35 2.15,1.75, height 0.55
PLS-2 [mm]
  round 2 hole 0.8: 1(0,0) 2(2.54,0)
SOD123F [mm] "Schottky Diode, 2-Leads, Body 3x2mm, 0.4W"
  rect 1.5x1 smd: 1(-1.375,0) 2(1.375,0)
  round 0.5 on Mech1: ""(1.5,0.5)
  silkscreen extent -2.4,-0.9 2.4,1, body extent -1.87,-0.85 1.88,0.85, height 1.23
SOD323 [mm]
  rect 0.85x0.5 smd: 1(-1.3,0) 2(1.3,0)
  round 0.5 on Mech1: 5(0.7,0.2)
  silkscreen extent -1.9,-0.7 1.9,0.7, body extent -1.15,-0.6 1.15,0.6, height 1.04
SOT23_123 [mm] "SOT23, 3-Leads, Body 3,0x2,6mm (max), Pitch 0,95mm, IPC Medium Density"
  rect 1x0.6 smd: 1(-1.2,0.95) 2(1.2,0) 3(-1.2,-0.95)
  round 0.5 on Mech1: ""(-0.9,1.1)
  silkscreen extent -1.32,-1.5 0.7,1.92, body extent -1.32,-1.52 1.32,1.52, height 1.12
SOT23_132 [mm] "SOT23, 3-Leads, Body 3,0x2,6mm (max), Pitch 0,95mm, IPC Medium Density"
  rect 1x0.6 smd: 1(-1.2,0.95) 2(-1.2,-0.95) 3(1.2,0)
  round 0.5 on Mech1: ""(-0.9,1.1)
  silkscreen extent -1.32,-1.5 0.7,1.92, body extent -1.32,-1.52 1.32,1.52, height 1.12
SOT223 [mm] "SOT223, 4-Leads, Body 6,50x7,00mm (avg), Pitch 2,30mm, IPC Medium Density"
  rect 2.4x1 smd: 1(-2.9,2.3) 2(-2.9,0) 3(-2.9,-2.3)
  rect 2.4x3.3 smd: 4(2.9,0)
  round 0.5 on Mech1: ""(-3,2.7)
  silkscreen extent -3.02,-3.2 1.3,3.47, body extent -3.48,-3.25 3.48,3.25, height 1.65
TANTAL_A [mm]
  rect 1.2x1.6 smd: 1(-1.6,0) 2(1.6,0)
  round 0.5 on Mech1: ""(-1.2,0.4)
  silkscreen extent -2.5,-1.1 2.5,1.1, body extent -1.7,-0.84 1.7,0.84, height 1.71
TANTAL_B [mm]
  rect 1.4x2.4 smd: 1(-1.75,0) 2(1.75,0)
  round 0.5 on Mech1: ""(-1.4,1)
  silkscreen extent -2.7,-1.5 2.7,1.5, body extent -1.85,-1.46 1.85,1.47, height 2.03
TANTAL_C [mm]
  rect 1.6x3.2 smd: 1(-3,0) 2(3,0)
  round 0.5 on Mech1: ""(-2.5,1.1)
  silkscreen extent -4.1,-1.9 4.1,1.9, body extent -3.05,-1.67 3.05,1.68, height 2.7
TANTAL_D [mm]
  rect 2x4.3 smd: 1(-3.85,0) 2(3.85,0)
  round 0.5 on Mech1: ""(-3.1,1.8)
  silkscreen extent -5.15,-2.5 5.15,2.5, body extent -3.7,-2.22 3.7,2.23, height 3.01
TestPoint#1 [mm]
  round 1 smd: 0(0,0)
TestPoint#2 [mm]
  round 1 smd: 0(0.926,0)
TL1014BF160QG [mm]
  rect 1.2x1 smd: 1(-2.8,-0.525) 1(2.8,-0.525) 2(-2.8,-2.225) 2(2.8,-2.225)
  round 0.6 on Top Overlay mask+0.05: 360(4,-0.475)
  round 0.8 hole 0.8: N(0,0) N(0,-2.75)
  body extent -3.2,-4.13 3.2,0.37, height 1.65

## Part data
C1 C2 C3 C4 C5 C6 C7 C8 C9 C10 C11 C12 C13 C14 C15 C16 C17 C19 C20 C21 C22 C23 C24 C25 C26 C28 C32 C33: library part Capacitor
C18 C27 C34 C35 C36: library part TantalCap
D1: "Cortex-M3", Manufacturer=STMicroelectronics
D2: "RS485", Manufacturer="Analog Devices Inc."
D6: library part LDL1117S33R, "LDO", Manufacturer=STMicroelectronics
DA1: library part LM2623AMMX
DA2: library part OP295
L1: library part Inductor
R1 R2 R3 R4 R5 R6 R7 R8 R9 R10 R11 R12 R13 R14 R15 R16 R17 R18 R19 R20 R21 R22 R23 R24 R25 R26 R27 R28 R29 R30 R31 R38 R42 R43 R50 R54 R55 R56 R57 R58 R59 R60 R61 R62 R63 R64 R65 R66 R67 R68 R69 R70 R71 R72 R73 R74 R75 R76 R77 R78 R79 R80 R81 R82 R83 R84 R85 R86 R87 R88 R89 R90 R91 R92 R93 R94 R95 R96 R97 R98 R99 R100 R101 R102 R103 R104 R105 R106 R107 R108 R109 R110 R111 R112 R113 R114 R115 R116 R117: library part Resistor
SB1 SB2 SB3 SB4 SB5: library part "Tactile switches", "6x6 mm"
TP1 TP2 TP3 TP4 TP5 TP6 TP7 TP8 TP9: library part TestPoint
VD1 VD2 VD8 VD22 VD23 VD24 VD25: library part "Diod Schottky"
VD3: library part "Diod Schottky Array v.1"
VD4: library part "TVS Array"
VD5 VD18 VD19 VD20 VD21 VD26 VD27 VD28 VD29 VD30 VD31 VD32 VD33 VD34: library part LED_1
VD6 VD9 VD13 VD17: library part Diod, Part Num=SMAF5.0A
VD7: library part Diod
VT1 VT2 VT3 VT4 VT5 VT6 VT7 VT8 VT9 VT14 VT15 VT16 VT17 VT18 VT19: library part N-chanel, "Mosfet"
VT10 VT11 VT12 VT13: library part P-chanel, "Mosfet"
X2: library part 10-Connector
X3: library part 4-Connector
X4: library part 30-Connector
X5 X15: library part 2-Connector
X6: library part 6(2)-Connector
X7: library part 14-Connector
X8: library part 8-Connector
X11: library part 3-Connector
Z1: library part Oscillator

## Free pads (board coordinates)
  round 0.6 hole 0.3 mask+0.05: N(2,50) N(2,55) N(2,60) N(2,65) N(2,70) N(2,75) N(2,80) N(2,85) N(2,90) N(2,95) N(2,100) N(2,105) N(8,65) N(8,70) N(8,75) N(8,80) N(8,85) N(8,90) N(8,95) N(8,100) N(8,105) N(14,65) N(14,70) N(14,75) N(14,80) N(14,85) N(14,90) N(14,95) N(14,100) N(14,105) N(20,65) N(20,70) N(20,75) N(26,65) N(26,70) N(26,75) N(33,6) N(33,9) N(37,6) N(37,9) N(41,6) N(41,9) N(45,9) N(45.675,56.475) N(46.825,57.55) N(47.5,17.5) N(49,19) N(50.5,17.5) N(52,19) N(54.5,19) N(56,17.5) N(57.1,19) N(67,31) N(69,26) N(71,31) N(73,26) N(107,80) N(107,85) N(107,90) N(107,95) N(107,100) N(107,105) N(113,80) N(113,85) N(113,90) N(113,95) N(113,100) N(113,105) N(119,80) N(119,85) N(119,90) N(119,95) N(119,100) N(119,105)
  round 10 hole 7 mask+0.05: N(5.5,5.5) N(5.5,115.5) N(115.5,5.5) N(115.5,115.5)
  rect 0.8x0.8 smd mask+0.05: N(18.225,34.35) N(40.625,41.925) N(40.628,44.006)
  round 7 hole 7 mask+0.05: N(60.5,44.5)

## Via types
v1: diameter 0.6, hole 0.3, Top Layer to Bottom Layer, tented both sides, 85 vias
v2: diameter 0.8, hole 0.4, Top Layer to Bottom Layer, tented both sides, 42 vias
v3: diameter 0.4, hole 0.2, Top Layer to Bottom Layer, tented both sides, 4 vias
v4: diameter 0.6, hole 0.3, Top Layer to Bottom Layer, 1 vias

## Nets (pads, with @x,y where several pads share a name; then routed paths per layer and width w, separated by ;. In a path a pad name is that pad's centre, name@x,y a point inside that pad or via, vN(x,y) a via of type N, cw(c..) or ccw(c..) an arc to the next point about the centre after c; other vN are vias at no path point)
3.3V: C2.2 C3.2 C5.2 C6.2 C7.2 C8.2 C14.2 C15.2 C16.2 C17.2 C28.2 C35.1 D1.1@28.375,30.4 D1.13 D1.19 D1.32 D1.48 D1.64 D2.8 D6.2 D6.4 R2.2 R42.2 R114.2 R115.2 R116.2 R117.2 VD1.2 X1.2 X4.24 X4.26 | length 382.5
  Top Layer w0.3: C2.2@25.5,22.3 25.712,22.512 26.174,22.512 26.35,22.688 26.35,23.475 27.275,24.4 D1.13@28.375,24.4 ; C8.2@26.075,31.15 26.075,30.576 26.251,30.4 D1.1@28.375,30.4 ; C3.2@29.8,34.5 29.95,34.35 29.95,33.65 30.325,33.275 D1.64@30.325,32.35 ; C7.2@31.099,18.549 31.325,18.775 D1.19@31.325,20.95 ; 37.825,20.2 D1.32@37.825,20.95 38.5,20.95 39.5,19.95 39.5,18.625 C6.2@39.45,18.575 ; D1.48@39.775,30.4 41.275,30.4 41.6,30.725 C5.2@42.975,30.725 ; C16.2@47.975,60.375 47.975,62.7 49.4,64.125 54.775,64.125 55.2,63.7 X4.26@55.2,59.25 55.2,57.9 55.2,57.425 ; C14.2@54.725,56.35 55,56.625 55,57.225 55.2,57.425 ; X4.24@56.2,59.25 56.2,57.601 56.024,57.425 55.2,57.425
  Top Layer w0.6: R2.2@5,38.9 5,36.975 11.5,30.475 v2(15.625,30.475) ; C15.2@54.725,54.725 54.75,54.7 v2(54.75,53.8) ; C28.2@76.425,17.875 76.425,16.251 76.074,15.9 D2.8@74.83,15.9 74.83,14.795 75.175,14.45 75.175,13.925 R42.2@75.1,13.85 76.75,13.85 77,14.1 77.1,14.1 v2(84.325,21.325)
  Top Layer w0.8: v2(21.05,25.1) 20.575,25.575 20.575,29.9 23.8,33.125 26.075,33.125 ; v2@21.075,25.1 21.075,24.125 22.9,22.3 ; VD1.2@23,17.95 22.9,18.05 22.9,22.3 ; C8.2@26.075,31.15 26.075,33.125 ; C7.2@31.099,18.549 31.099,17.25 ; C6.2@39.45,18.575 39.45,17.425 39.625,17.25 ; v2(42.375,62.45) 44.45,60.375 C17.2@46,60.375 47.975,60.375 C16.2@48,60.375 ; C5.2@42.975,30.725 C5.2@43,30.7 44.625,30.7 45.54,31.615 X1.2@45.54,34 45.246,34 41.696,37.55 32.15,37.55 29.825,35.225 29.825,34.525 C3.2@29.8,34.5 27.45,34.5 26.075,33.125 ; C15.2@54.725,54.725 C14.2@54.725,56.35 ; D6.4@59.875,15.4 D6.2@54.075,15.4 43.275,15.4 41.425,17.25 39.625,17.25 ; v2(84.275,55.725) 85.325,54.675 v2(85.325,52.625) ; v2(85.325,33.35) v2(85.325,36.55) ; 22.9,22.3 C2.2@25.5,22.3 25.5,19.125 27.375,17.25 31.099,17.25 ; 31.099,17.25 39.625,17.25
  Top Layer w1: D6.4@59.875,15.4 60.425,15.95 60.425,17.825 60.888,18.287 ; C35.1@61.275,20.7 61.275,18.675 60.888,18.287 ; v2(62,17.975) 61.688,18.287 60.888,18.287
  Bottom Layer w0.6: v2(15.625,30.475) 21,25.1 v2(21.05,25.1) 21.104,25.1 21.654,24.55 23.274,24.55 23.625,24.901 23.625,26.675 R117.2@23.5,26.8 ; v2(54.75,53.8) 73.075,53.8 76.2,56.925 84.275,56.925 v2(84.275,55.725)
  Bottom Layer w0.8: R115.2@26.9,59.9 26.9,61.631 27.719,62.45 v2(42.375,62.45) ; 84.275,23.675 84.275,21.325 88.775,16.825 114.575,16.825 117.825,20.075 117.825,26.75 111.55,33.025 96.775,33.025 93.342,29.592 88.433,29.592 85.325,32.7 v2(85.325,33.35) ; 84.3,23.7 R116.2@84.3,26.9 ; v2(85.325,36.55) v2(85.325,52.625)
  Bottom Layer w1: v2(62,17.975) 68.925,17.975 77.85,26.9 R116.2@84.3,26.9
5/10V_OUT: D1.17 R13.2 | length 53.1
  Top Layer w0.3: R13.2@4.6,53.275 4.612,53.262 4.612,50.188 v1(6.8,48) ; v1(29,21.375) 29.081,21.375 29.506,20.95 D1.17@30.325,20.95
  Bottom Layer w0.3: v1(6.8,48) 6.8,42.57 2.75,38.52 2.75,36.95 4.125,35.575 5.75,35.575 19.95,21.375 v1(29,21.375)
5V: C18.1 C20.2 C24.2 C32.2 C33.2 C34.1 D6.3 DA1.6 DA1.7 L1.2 R3.2 R11.1 R18.1 R29.1 R54.2 R55.2 R56.2 R57.2 R96.2 R97.2 R105.2 R106.2 R107.2 VD2.2 VD3.2 VD6.2 VD17.2 X3.1 X6.1 X8.1 X15.1 | length 461.1
  Top Layer w0.4: DA1.7@29.75,54.375 DA1.6@29.75,53.725 31.65,53.725 C24.2@31.85,53.525
  Top Layer w0.6: VD3.2@3.777,22.266 3.777,18.789 4.175,18.391 7.075,18.391 8.415,19.731 X3.1@11.725,19.731 ; v2(7.75,44.35) 7.75,39.3 8.85,38.2 12.074,38.2 12.425,37.849 12.425,37.3 R29.1@12.375,37.25 ; C32.2@53.375,20.7 C33.2@50.975,20.7 50.975,22.85 52.9,24.775 55.95,24.775 56.35,25.175 56.35,27.525 R3.2@56.425,27.6 ; R55.2@82.775,62.925 82.787,62.912 84.613,62.912 v2(84.625,62.9) ; v2(102.3,29) 103.675,27.625 VD17.2@108.275,27.625 109.775,27.625 111.175,29.025 ; v2(112.7,62.9) 112.7,60.825 111.3,59.425 111.3,29.15 111.175,29.025 ; X8.1@115.15,25.175 111.3,29.025 111.175,29.025
  Top Layer w0.8: VD6.2@14.3,22.45 14.3,20.199 13.831,19.731 X3.1@11.725,19.731 11.725,8.05 16.55,3.225 VD2.2@25.2,3.225 ; v2(18.875,50.375) 19.775,49.475 20.8,49.475 R11.1@20.825,49.45 20.85,49.425 20.85,48.325 22.175,47 27.106,47 28.006,47.9 28.675,47.9 R18.1@28.7,47.925 C18.1@30.675,47.925 ; C18.1@30.975,47.6 31.275,47.3 31.275,46.094 31.744,45.625 35.41,45.625 36.825,47.04 ; C24.2@31.85,53.525 C20.2@33.575,53.525 ; v2(40.65,58.975) 39.325,60.3 L1.2@32.95,60.3 ; X6.1@46.96,47.04 36.825,47.04 ; C32.2@53.375,20.7 53.375,22.956 53.844,23.425 62.375,23.425 63.9,21.9 63.9,13.35 62.525,11.975 56.5,11.975 55.475,13 54.175,13 D6.3@54.075,13.1 ; R55.2@82.775,62.925 R57.2@80.775,62.925 R56.2@78.775,62.925 R54.2@76.775,62.925 71.353,62.925 70.978,63.3 70.942,63.3 69.393,64.85 35.775,64.85 33.125,62.2 33.125,60.475 L1.2@32.95,60.3 ; L1.2@32.95,60.3 32.95,56.9 33.575,56.275 C20.2@33.575,53.525 ; C20.2@33.575,53.525 34.85,53.525 36.825,51.55 36.825,47.04
  Top Layer w1: VD2.2@25.2,3.225 25.248,3.225 25.248,1.902 26.1,1.05 53.575,1.05 X15.1@55.925,3.4 55.925,6.225 55.325,6.825 C34.1@55.325,9.9 55.325,10.4 55.125,10.6 54.161,10.6 53.575,11.186 53.575,13.1 D6.3@54.075,13.1
  Bottom Layer w0.3: R107.2@39,29 40.775,29 43.65,31.875 48.1,31.875 48.376,32.151 48.376,36.309 43.575,41.109 43.575,44.495 43.55,44.52 43.55,46.7 45.75,48.9 49.625,48.9 50.85,47.675 50.85,45.976 50.674,45.8 47.136,45.8 47.136,46.864 X6.1@46.96,47.04
  Bottom Layer w0.6: v2(7.75,44.35) 12.85,44.35 19.5,51 R105.2@21,51 ; v2(84.625,62.9) 88.525,62.9 91.6,65.975 100.425,65.975 102.625,63.775 102.625,59.6 102.025,59 ; R106.2@100,29 v2(102.3,29) ; R96.2@100,59 102.025,59 ; v2(112.7,62.9) 112.646,62.9 111.801,63.745 109.845,63.745 105.1,59 102.025,59
  Bottom Layer w0.8: v2(7.75,44.35) 7.75,49 7.281,49.469 6.619,49.469 5.675,48.525 5.675,43.35 1.925,39.6 1.925,27.3 3.85,25.375 7.95,25.375 9.65,23.675 9.65,20.119 10.119,19.65 11.644,19.65 X3.1@11.725,19.731 ; R97.2@39,59 40.625,59 v2(40.65,58.975)
12V: C10.2 C11.2 C22.2 C26.2 C27.1 DA2.8 R25.1 R28.1 R30.1 VD8.2 X4.3 X4.29 | length 159.5
  Top Layer w0.3: C10.2@51.725,56.8 51.75,56.825 51.75,57.849 51.926,58.025 ; X4.29@53.7,59.25 53.7,58.201 53.524,58.025 51.926,58.025 ; v1(54.025,63.4) 54,63.425 50.075,63.425 49.55,62.9 49.55,59.15 50.675,58.025 51.926,58.025 ; v1(65.7,63.4) 66.7,62.4 X4.3@66.7,59.25 66.7,57.7 67,57.4 67.974,57.4 68.15,57.224 C11.2@68.15,56.775
  Top Layer w0.6: v2(6.8,41.3) 6.8,38.45 R28.1@9.225,36.025 ; C22.2@9.5,56.075 9.5,59 10.275,59.775 C27.1@12.55,59.775 ; C27.1@13.7,59.775 v2(20.575,59.775) 22.575,57.775 25.15,57.775 VD8.2@25.275,57.9 ; DA2.8@20.208,42.804 21.167,42.804 21.221,42.75 v2(21.275,42.75) 21.3,42.775 22.617,42.775 R30.1@22.646,42.804
  Top Layer w0.8: v2(10.925,50.05) 16.1,50.05 20.675,45.475 v2(26.25,45.475) ; v2(10.975,56.7) 11.95,57.675 11.95,59.175 12.55,59.775 C27.1@13.7,59.775 ; R25.1@22.95,49.45 22.975,49.425 22.975,48.719 23.444,48.25 24.975,48.25 25.025,48.2 26.175,48.2 v2(26.275,48.1)
  Bottom Layer w0.3: v2(20.575,59.775) 20.575,61.525 22.45,63.4 v1(54.025,63.4) v1(65.7,63.4)
  Bottom Layer w0.6: v2(6.8,41.3) 8.304,42.804 20.575,42.804 20.591,42.788 21.237,42.788 v2(21.275,42.75)
  Bottom Layer w0.8: v2(10.925,50.05) 10.925,56.65 v2(10.975,56.7) ; v2(21.275,42.75) 21.275,41.644 21.744,41.175 24.85,41.175 26.275,42.6 26.275,45.45 v2(26.25,45.475) 26.275,45.5 v2(26.275,48.1)
ADC0: C21.2 D1.9 R14.1 | length 23.8
  Top Layer w0.3: v1(21.475,38.175) 21.61,38.175 21.835,38.4 22.425,38.4 C21.2@22.825,38.8 ; D1.9@28.375,26.4 29.619,26.4 32.019,28.8 v1(32.1,28.8)
  Top Layer w0.6: C21.2@22.825,38.8 23.3,38.8 23.975,39.475 23.975,40.125 R14.1@24.1,40.25
  Bottom Layer w0.3: v1(21.475,38.175) 23.9,38.175 32.1,29.975 v1(32.1,28.8)
ADC1: D1.10 R23.1 R28.2 | length 25.2
  Top Layer w0.3: R23.1@10.85,33.675 10.975,33.55 11.075,33.55 11.075,32.728 11.853,31.95 v1(11.975,31.95) ; v1(23.975,24.15) 24.425,24.6 26.201,24.6 27.501,25.9 D1.10@28.375,25.9
  Top Layer w0.6: R28.2@9.225,34.475 9.225,34.026 9.576,33.675 R23.1@10.85,33.675
  Bottom Layer w0.3: v1(11.975,31.95) 20.2,23.725 23.469,23.725 23.894,24.15 v1(23.975,24.15)
ADC2: D1.11 R24.1 R29.2 | length 33.8
  Top Layer w0.3: R29.2@10.96,37.234 R29.2@10.975,37.25 10.975,36.475 v1(13.65,36.475) ; D1.11@28.375,25.4 30.075,25.4 v1(32.95,28.275)
  Top Layer w0.6: R24.1@10.944,35.491 10.96,35.506 10.96,36.475 R29.2@10.96,37.234
  Bottom Layer w0.3: v1(13.65,36.475) 22,28.125 32.719,28.125 32.869,28.275 v1(32.95,28.275)
AIN: R27.1 R30.2 R31.1 X7.1 | length 142.5
  Top Layer w0.3: R31.1@25.8,42.8 31.95,42.8 34.7,40.05 46.3,40.05 49.05,37.3 68.224,37.3 68.4,37.476 68.4,49.6 74.975,56.175 74.975,61.524 75.376,61.925 86.475,61.925 v2(95.85,71.3)
  Top Layer w0.6: R27.1@18.575,37.35 18.575,43.499 18.926,43.85 23.599,43.85 23.95,43.499 23.95,42.925 R30.2@24.075,42.8 R31.1@25.8,42.8
  Bottom Layer w0.3: v2(95.85,71.3) 100.95,71.3 105.975,66.275 113.675,66.275 114.975,64.975 X7.1@114.975,55.125
BOOT: C9.2 D1.60 D1.61 R1.2 X1.1 | length 19.8
  Top Layer w0.3: D1.61@31.825,32.35 D1.60@32.325,32.35 32.325,31.501 32.501,31.325 38.3,31.325 39.55,32.575 39.55,32.825 40.725,34 X1.1@43,34
  Top Layer w0.8: R1.2@37.5,36.2 C9.2@39.5,36.2 40.8,36.2 X1.1@43,34
BS0: R7.2 X4.16 | length 4.1
  Top Layer w0.3: X4.16@60.2,59.25 60.2,58.25 61.2,57.25 61.874,57.25 62.05,57.074 R7.2@62.05,56.275
BS1: R8.2 X4.17 | length 3.4
  Top Layer w0.3: X4.17@59.7,59.25 59.7,58 60.65,57.05 R8.2@60.65,56.275
CS: D1.56 X4.19 | length 43.2
  Top Layer w0.3: D1.56@34.325,32.35 34.325,33.475 34.618,33.768 34.618,34.293 v1(34.675,34.35) ; X4.19@58.7,59.25 58.7,58.125 v1(59.225,57.6)
  Bottom Layer w0.3: v1(34.675,34.35) 34.675,41.55 51.7,58.575 58.25,58.575 v1(59.225,57.6)
DAC: D1.20 R15.2 | length 37.3
  Top Layer w0.3: v1(9.15,39.6) 9.231,39.6 9.331,39.7 10.525,39.7 R15.2@10.55,39.725 ; v1(29.025,22.175) 29.75,22.175 30.5,22.925 31.649,22.925 31.825,22.749 D1.20@31.825,20.95
  Bottom Layer w0.3: v1(9.15,39.6) 9.15,33.175 20.15,22.175 v1(29.025,22.175)
DS: D1.58 X4.18 | length 46.6
  Top Layer w0.3: D1.58@33.325,32.35 33.325,34.144 33.425,34.244 v1(33.425,34.325) ; X4.18@59.2,59.25 v1(59.2,62.1)
  Bottom Layer w0.3: v1(33.425,34.325) 33.425,41.975 53.55,62.1 v1(59.2,62.1)
ENC_A: D1.22 X6.5 | length 50
  Top Layer w0.3: v1(32.8,18.9) 32.825,18.925 D1.22@32.825,20.95 ; v1(44.825,41.825) 44.906,41.825 45.061,41.98 46.94,41.98 X6.5@46.96,41.96
  Bottom Layer w0.3: v1(32.8,18.9) 32.8,16.975 33.2,16.575 41.2,16.575 55.075,30.45 55.075,31.05 44.882,41.243 44.882,41.768 v1(44.825,41.825)
ENC_B: D1.23 X6.2 | length 58
  Top Layer w0.3: D1.23@33.325,20.95 33.325,19.3 33.45,19.175 v1(33.45,18.375) ; X6.2@49.5,46.9 X6.2@49.5,47.04
  Bottom Layer w0.3: v1(33.45,18.375) 33.45,17.276 33.626,17.1 40.95,17.1 54.35,30.5 54.35,30.971 44.1,41.221 44.1,42.6 45.6,44.1 45.6,47.925 46.05,48.375 49.3,48.375 49.5,48.175 X6.2@49.5,47.04
ENC_KEY: D1.21 X6.3 | length 53
  Top Layer w0.3: v1(32.175,18.425) 32.175,19.175 32.325,19.325 D1.21@32.325,20.95
  Bottom Layer w0.3: v1(32.175,18.425) 32.175,16.575 32.7,16.05 41.425,16.05 55.65,30.275 55.65,31.4 45.6,41.45 45.6,43.14 X6.3@46.96,44.5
